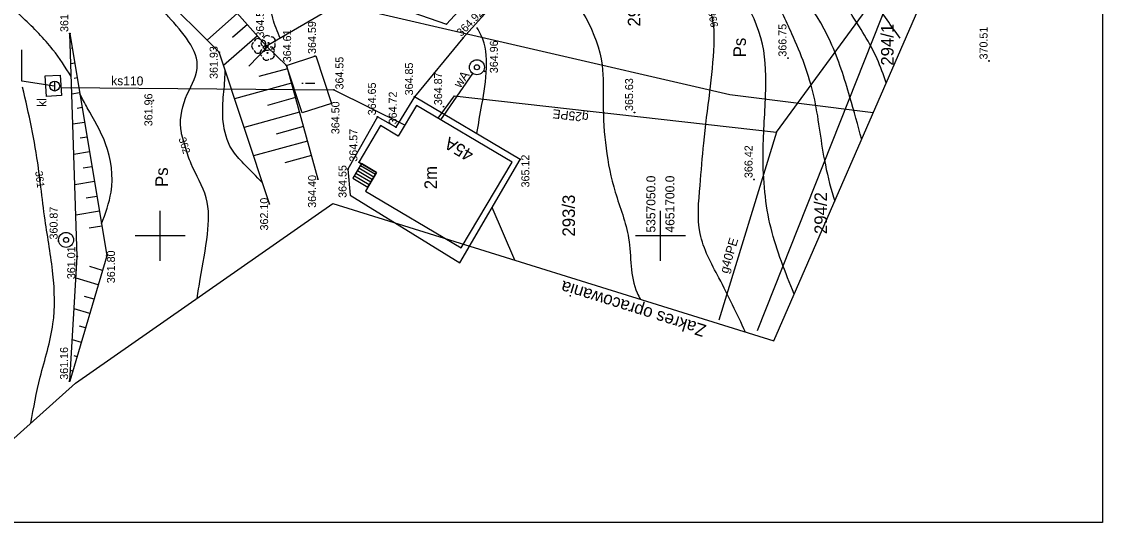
# Model space of a CAD drawing. Extents: x 4635329 to 4651863, y 5356628 to 5367582.
# Drawn here: x 4651223.2 to 4651331.2, y 5356627.7 to 5356677.8 of the extents above; entities that cross this region are included whole.
import ezdxf

# ---------------------------------------------------------------- set-up
doc = ezdxf.new("R2010")
doc.units = 0
for name, color, linetype in [('Level 1', 7, 'Continuous'), ('Level 12', 7, 'Continuous'), ('Level 13', 7, 'Continuous'), ('Level 14', 7, 'Continuous'), ('Level 15', 7, 'Continuous'), ('Level 20', 7, 'Continuous'), ('Level 22', 7, 'Continuous'), ('Level 35', 7, 'Continuous'), ('Level 36', 7, 'Continuous'), ('Level 37', 7, 'Continuous'), ('Level 39', 7, 'Continuous'), ('Level 4', 7, 'Continuous'), ('Level 44', 7, 'Continuous'), ('Level 45', 7, 'Continuous'), ('Level 46', 7, 'Continuous'), ('Level 47', 7, 'Continuous'), ('Level 48', 7, 'Continuous'), ('Level 5', 7, 'Continuous'), ('Level 54', 7, 'Continuous'), ('Level 55', 7, 'Continuous'), ('Level 58', 7, 'Continuous'), ('Level 6', 7, 'Continuous'), ('Level 60', 7, 'Continuous')]:
    doc.layers.add(name, color=color, linetype=linetype)

msp = doc.modelspace()

# ---------------------------------------------------------------- linework, layer by layer
at = {"layer": 'Level 1'}
for p, q in [((4651298.354, 5356645.8610000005), (4651316.177, 5356686.717)), ((4651228.549, 5356641.621), (4651254.266, 5356659.569)), ((4651254.266, 5356659.569), (4651298.354, 5356645.8610000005)), ((4651216.704, 5356631.078), (4651228.549, 5356641.621))]:
    msp.add_line(p, q, dxfattribs=at)
at = {"layer": 'Level 13'}
for points in [[(4651092.18, 5356627.729), (4651092.18, 5356813.355), (4651331.195, 5356813.355), (4651331.195, 5356627.729)], [(4651272.195, 5356663.717), (4651262.635, 5356669.387), (4651260.818, 5356666.323), (4651259.036, 5356667.38), (4651256.87, 5356663.728), (4651258.633, 5356662.682), (4651257.536, 5356660.833000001), (4651267.112, 5356655.151000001)], [(4651272.195, 5356663.717), (4651272.195, 5356663.717)]]:
    msp.add_lwpolyline(points, close=True, dxfattribs=at)
at = {"layer": 'Level 15'}
for p, q in [((4651257.141, 5356663.567), (4651256.273, 5356662.104)), ((4651256.886, 5356663.136), (4651258.3780000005, 5356662.25)), ((4651257.039, 5356663.394), (4651258.531, 5356662.508)), ((4651258.633, 5356662.682), (4651257.141, 5356663.567)), ((4651256.273, 5356662.104), (4651257.765, 5356661.218)), ((4651256.426, 5356662.362), (4651257.9180000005, 5356661.476)), ((4651256.579, 5356662.62), (4651258.071, 5356661.734)), ((4651256.733, 5356662.8780000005), (4651258.225000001, 5356661.992000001)), ((4651257.765, 5356661.218), (4651258.633, 5356662.682))]:
    msp.add_line(p, q, dxfattribs=at)
for points in [[(4651249.6450000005, 5356673.377), (4651252.5770000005, 5356674.333000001), (4651254.125, 5356669.587), (4651251.193, 5356668.631)], [(4651225.6450000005, 5356670.2870000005), (4651225.531, 5356672.323), (4651227.025, 5356672.407), (4651227.139, 5356670.371)]]:
    msp.add_lwpolyline(points, close=True, dxfattribs=at)
at = {"layer": 'Level 20'}
for points in [[(4651283.015, 5356700.977), (4651282.555, 5356699.227), (4651281.905, 5356696.897), (4651273.365, 5356685.887), (4651265.6450000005, 5356677.517)], [(4651267.255, 5356676.097), (4651275.075, 5356684.757), (4651285.735, 5356696.707), (4651287.285, 5356699.227)], [(4651256.195, 5356680.807), (4651265.6450000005, 5356677.517)], [(4651253.4350000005, 5356678.667), (4651247.655, 5356675.297)], [(4651267.255, 5356676.097), (4651262.4350000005, 5356670.237)]]:
    msp.add_lwpolyline(points, dxfattribs=at)
at = {"layer": 'Level 22'}
msp.add_lwpolyline([(4651273.005, 5356663.997), (4651262.4350000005, 5356670.237), (4651260.585, 5356667.207), (4651258.725000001, 5356668.247), (4651255.775, 5356663.017), (4651256.008, 5356660.426), (4651266.98, 5356653.641), (4651273.005, 5356663.997)], dxfattribs=at)
at = {"layer": 'Level 35'}
msp.add_lwpolyline([(4651265.066, 5356667.945), (4651268.25, 5356672.579)], dxfattribs=at)
at = {"layer": 'Level 36'}
msp.add_line((4651226.467, 5356670.82), (4651226.467, 5356671.82), dxfattribs=at)
msp.add_lwpolyline([(4651226.437, 5356671.29), (4651223.181, 5356671.8040000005), (4651223.181, 5356674.936)], dxfattribs=at)
msp.add_circle((4651226.466676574, 5356671.320149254), 0.5, dxfattribs=at)
at = {"layer": 'Level 37'}
msp.add_lwpolyline([(4651227.0940000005, 5356671.175), (4651254.375, 5356670.947), (4651261.4350000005, 5356667.457)], dxfattribs=at)
at = {"layer": 'Level 39'}
for points in [[(4651298.615, 5356666.727), (4651310.795, 5356683.3270000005)], [(4651266.3950000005, 5356670.357), (4651264.783, 5356668.113)], [(4651266.3950000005, 5356670.357), (4651298.615, 5356666.727), (4651292.866, 5356647.9180000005)]]:
    msp.add_lwpolyline(points, dxfattribs=at)
at = {"layer": 'Level 4'}
for p, q in [((4651296.735, 5356646.885), (4651312.251, 5356686.105)), ((4651293.945, 5356670.447), (4651252.965, 5356679.897)), ((4651308.288, 5356668.633), (4651293.945, 5356670.447))]:
    msp.add_line(p, q, dxfattribs=at)
at = {"layer": 'Level 44'}
for centre in [(4651265.6450000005, 5356677.517), (4651227.975000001, 5356676.567), (4651267.255, 5356676.097), (4651247.655, 5356675.297), (4651242.915, 5356674.697), (4651252.465, 5356674.297), (4651299.765, 5356674.107), (4651319.865, 5356673.8270000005), (4651319.865, 5356673.8270000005), (4651249.6450000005, 5356673.377), (4651269.447972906, 5356672.787698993), (4651254.375, 5356670.947), (4651236.325, 5356669.877), (4651254.125, 5356669.587), (4651262.4350000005, 5356670.237), (4651265.345, 5356669.257), (4651284.4350000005, 5356668.677), (4651258.725000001, 5356668.247), (4651260.585, 5356667.207), (4651273.005, 5356663.997), (4651255.775, 5356663.017), (4651256.905, 5356663.707), (4651252.775, 5356662.007), (4651296.375, 5356661.977), (4651247.925, 5356659.557), (4651226.833, 5356655.840658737), (4651228.725000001, 5356654.2870000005), (4651231.675, 5356654.347), (4651227.955, 5356641.8270000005)]:
    msp.add_circle(centre, 0.04, dxfattribs=at)
at = {"layer": 'Level 46'}
for p, q in [((4651292.399, 5356676.979), (4651292.041, 5356679.073)), ((4651239.818, 5356664.316000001), (4651239.172, 5356666.442)), ((4651225.09, 5356661.222), (4651224.855, 5356663.04)), ((4651272.465, 5356653.911), (4651270.197, 5356659.171))]:
    msp.add_line(p, q, dxfattribs=at)
for points in [[(4651300.394, 5356650.538), (4651298.071, 5356657.119), (4651297.283, 5356664.3950000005), (4651297.525, 5356670.398), (4651297.222, 5356675.491), (4651291.339, 5356684.404), (4651287.093, 5356687.193), (4651283.575, 5356689.133), (4651281.998, 5356690.892), (4651281.523, 5356691.985)], [(4651307.135, 5356665.99), (4651305.956, 5356670.216), (4651304.015, 5356675.733), (4651297.646, 5356685.192), (4651295.888, 5356687.799), (4651295.484, 5356688.617000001)], [(4651228.12, 5356672.269), (4651226.297, 5356674.945), (4651223.325, 5356678.098), (4651221.142, 5356680.341), (4651219.686, 5356682.766), (4651219.019, 5356684.282), (4651218.821, 5356685.129)], [(4651310.99, 5356676.097), (4651308.382, 5356679.796), (4651304.957, 5356685.363)], [(4651249.021, 5356676.093), (4651248.274, 5356678.101), (4651248.214, 5356681.739), (4651248.335, 5356683.6790000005), (4651248.335, 5356684.088)], [(4651274.444, 5356684.058), (4651276.507, 5356682.152), (4651281.177, 5356673.421), (4651281.298, 5356669.601), (4651282.502, 5356660.721), (4651283.836, 5356656.113), (4651284.6850000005, 5356650.656), (4651285.015, 5356650.008)], [(4651239.172, 5356666.442), (4651239.132, 5356666.654), (4651239.557, 5356670.11), (4651240.709, 5356673.081), (4651237.858, 5356678.235), (4651236.949, 5356679.265)], [(4651309.598, 5356671.636), (4651308.68, 5356674.0430000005), (4651306.011, 5356678.651000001), (4651305.441, 5356679.573)], [(4651299.187, 5356678.601), (4651300.134000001, 5356676.573), (4651302.317, 5356670.328), (4651303.409, 5356663.901000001), (4651304.313, 5356660.2190000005), (4651304.436, 5356659.8040000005)], [(4651268.653, 5356666.566000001), (4651269.171, 5356669.459), (4651269.626, 5356673.127), (4651269.1110000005, 5356676.371), (4651268.671, 5356677.176)], [(4651295.526000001, 5356646.74), (4651292.863, 5356652.156), (4651290.982, 5356656.583000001), (4651290.982, 5356661.373), (4651291.346, 5356665.617000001), (4651291.953, 5356670.71), (4651292.377, 5356675.44), (4651292.399, 5356676.979)], [(4651247.229, 5356661.659), (4651245.379, 5356663.562), (4651244.166, 5356665.017), (4651243.317, 5356667.745), (4651243.317, 5356670.171), (4651243.499, 5356672.475000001), (4651243.499, 5356672.932)], [(4651224.855, 5356663.04), (4651224.841, 5356663.146), (4651223.266, 5356671.212)], [(4651231.144, 5356657.5370000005), (4651232.097, 5356660.712), (4651231.551, 5356665.562), (4651229.731, 5356669.14), (4651228.979, 5356670.54)], [(4651240.707, 5356650.106), (4651241.012, 5356652.041), (4651241.74, 5356656.528), (4651241.619, 5356660.166), (4651240.103, 5356663.562), (4651239.818, 5356664.316000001)], [(4651224.079, 5356637.643), (4651225.023, 5356642.228), (4651226.297, 5356647.563), (4651226.297, 5356652.535), (4651225.508, 5356657.932), (4651225.09, 5356661.222)]]:
    msp.add_spline(points, degree=3, dxfattribs=at)
at = {"layer": 'Level 48'}
for p, q in [((4651244.742000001, 5356678.5940000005), (4651241.703, 5356675.909)), ((4651245.735, 5356677.47), (4651244.251, 5356676.158)), ((4651246.728, 5356676.346), (4651243.356, 5356673.365)), ((4651228.221, 5356675.087), (4651228.124, 5356675.071)), ((4651247.727, 5356675.227), (4651245.87, 5356673.302)), ((4651228.468, 5356673.608), (4651228.0770000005, 5356673.5430000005)), ((4651249.734, 5356673.0540000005), (4651246.858, 5356672.262)), ((4651228.714, 5356672.1280000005), (4651228.421, 5356672.079)), ((4651250.132, 5356671.607), (4651244.455, 5356670.044)), ((4651228.961, 5356670.648), (4651228.1790000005, 5356670.518)), ((4651250.53, 5356670.161), (4651247.728, 5356669.39)), ((4651229.207, 5356669.169), (4651228.718, 5356669.087)), ((4651250.928, 5356668.715), (4651245.398, 5356667.193)), ((4651229.453, 5356667.689), (4651228.28, 5356667.494)), ((4651251.3270000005, 5356667.269), (4651248.598, 5356666.518)), ((4651229.7, 5356666.21), (4651229.016, 5356666.096)), ((4651251.725000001, 5356665.823), (4651246.342, 5356664.341)), ((4651229.946, 5356664.73), (4651228.382, 5356664.47)), ((4651252.123, 5356664.376), (4651249.468, 5356663.646)), ((4651230.192, 5356663.25), (4651229.313, 5356663.104)), ((4651230.439, 5356661.771), (4651228.484, 5356661.445)), ((4651230.6850000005, 5356660.291), (4651229.61, 5356660.112)), ((4651230.932, 5356658.811), (4651228.586, 5356658.421)), ((4651231.178, 5356657.332), (4651229.907, 5356657.12)), ((4651231.675, 5356654.347), (4651227.995, 5356641.8270000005)), ((4651227.995, 5356641.8270000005), (4651228.725000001, 5356654.247)), ((4651231.252, 5356652.908), (4651229.971, 5356653.284)), ((4651230.829, 5356651.4690000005), (4651228.600000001, 5356652.124)), ((4651230.406, 5356650.03), (4651229.458, 5356650.308)), ((4651229.983, 5356648.591), (4651228.42, 5356649.05)), ((4651229.5600000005, 5356647.151000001), (4651228.945, 5356647.332)), ((4651229.137, 5356645.712), (4651228.239, 5356645.976)), ((4651228.714, 5356644.273), (4651228.431, 5356644.356)), ((4651228.291, 5356642.834), (4651228.058, 5356642.903))]:
    msp.add_line(p, q, dxfattribs=at)
for points in [[(4651247.925, 5356659.557), (4651242.915, 5356674.697), (4651236.735, 5356680.877), (4651232.205, 5356686.657)], [(4651232.205, 5356686.657), (4651243.325, 5356680.197), (4651247.655, 5356675.297), (4651249.6450000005, 5356673.377), (4651252.775, 5356662.007)], [(4651228.725000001, 5356654.2870000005), (4651227.975000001, 5356676.567)], [(4651227.975000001, 5356676.567), (4651231.675, 5356654.347)]]:
    msp.add_lwpolyline(points, dxfattribs=at)
at = {"layer": 'Level 54'}
for centre, radius in [((4651268.675, 5356673.197), 0.7499999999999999), ((4651268.675, 5356673.197), 0.25000000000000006), ((4651227.605, 5356655.947), 0.7500000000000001), ((4651227.605, 5356655.947), 0.25)]:
    msp.add_circle(centre, radius, dxfattribs=at)
at = {"layer": 'Level 55'}
for centre in [(4651246.89837069, 5356675.322033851), (4651247.838258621, 5356675.6251262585), (4651247.747301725, 5356674.624921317)]:
    msp.add_circle(centre, 0.045, dxfattribs=at)
for centre, start, end in [((4651246.782370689, 5356675.678533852), 48.19845000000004, 167.84984166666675), ((4651247.463258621, 5356675.6251262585), 120.14713055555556, 239.85286944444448), ((4651247.201870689, 5356675.542533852), 336.10841111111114, 95.89019166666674), ((4651247.722258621, 5356675.981626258), 48.19845000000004, 167.84984166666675), ((4651248.141758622, 5356675.845626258), 336.10841111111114, 95.89019166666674), ((4651246.52337069, 5356675.322033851), 120.14713055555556, 239.85286944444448), ((4651246.782370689, 5356674.965533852), 192.15015833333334, 311.80155), ((4651247.372301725, 5356674.624921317), 120.14713055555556, 239.85286944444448), ((4651247.201870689, 5356675.101533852), 264.1076444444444, 23.89158888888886), ((4651247.631301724, 5356674.981421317), 48.19845000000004, 167.84984166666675), ((4651247.722258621, 5356675.268626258), 192.15015833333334, 311.80155), ((4651248.050801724, 5356674.845421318), 336.10841111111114, 95.89019166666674), ((4651248.141758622, 5356675.404626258), 264.1076444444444, 23.89158888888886), ((4651247.631301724, 5356674.268421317), 192.15015833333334, 311.80155), ((4651248.050801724, 5356674.404421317), 264.1076444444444, 23.89158888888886)]:
    msp.add_arc(centre, 0.375, start, end, dxfattribs=at)
at = {"layer": 'Level 60'}
for p, q in [((4651237.015, 5356653.847), (4651237.015, 5356658.847)), ((4651287.015, 5356653.847), (4651287.015, 5356658.847)), ((4651239.515, 5356656.347), (4651234.515, 5356656.347)), ((4651289.515, 5356656.347), (4651284.515, 5356656.347))]:
    msp.add_line(p, q, dxfattribs=at)

# ---------------------------------------------------------------- texts
at = {"layer": 'Level 12'}
for p in [(4651295.5600000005, 5356674.194), (4651237.791, 5356661.238)]:
    msp.add_text('Ps', height=1.2499980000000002, rotation=90, dxfattribs=at).set_placement(p)
at = {"layer": 'Level 14'}
for s, p in [('i', (4651252.483, 5356671.409)), ('2m', (4651264.671, 5356661.006))]:
    msp.add_text(s, height=1.2499980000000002, rotation=90, dxfattribs=at).set_placement(p)
at = {"layer": 'Level 35'}
msp.add_text('wA', height=0.9, rotation=55.507222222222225, dxfattribs=at).set_placement((4651267.025, 5356671.0540000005))
at = {"layer": 'Level 37'}
for s, height, rotation, p in [('ks110', 0.8999880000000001, 359.5211638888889, (4651232.115, 5356671.402)), ('kl', 0.9, 90, (4651225.62, 5356669.246))]:
    msp.add_text(s, height=height, rotation=rotation, dxfattribs=at).set_placement(p)
at = {"layer": 'Level 39'}
for s, rotation, p in [('g25PE', 173.57199444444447, (4651279.875, 5356668.600000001)), ('g40PE', 73.00414722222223, (4651293.754, 5356652.533))]:
    msp.add_text(s, height=0.8999880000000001, rotation=rotation, dxfattribs=at).set_placement(p)
at = {"layer": 'Level 45'}
for s, rotation, p in [('361.77', 90, (4651227.825, 5356676.717)), ('364.56', 90, (4651247.399, 5356676.159)), ('364.92', 45.84554722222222, (4651267.116, 5356676.214)), ('364.59', 90, (4651252.587, 5356674.522)), ('366.75', 90, (4651299.615, 5356674.257)), ('370.51', 90, (4651319.715, 5356673.977)), ('370.51', 90, (4651319.715, 5356673.977)), ('364.61', 90, (4651250.101, 5356673.694)), ('361.93', 90, (4651242.765, 5356672.032)), ('364.96', 90, (4651270.769, 5356672.604)), ('364.55', 90, (4651255.331, 5356670.976)), ('364.85', 90, (4651262.285, 5356670.387)), ('364.87', 90, (4651265.195, 5356669.407)), ('364.65', 90, (4651258.575, 5356668.397)), ('365.63', 90, (4651284.285, 5356668.8270000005)), ('361.96', 90, (4651236.2360000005, 5356667.302)), ('364.72', 90, (4651260.6620000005, 5356667.494)), ('364.50', 90, (4651254.9290000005, 5356666.511)), ('364.57', 90, (4651256.725000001, 5356663.766)), ('366.42', 90, (4651296.225000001, 5356662.127)), ('365.12', 90, (4651273.916, 5356661.191000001)), ('364.55', 90, (4651255.64, 5356660.151000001)), ('364.40', 90, (4651252.595, 5356659.159)), ('362.10', 90, (4651247.805, 5356656.892)), ('360.87', 90, (4651226.759000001, 5356655.991)), ('361.01', 90, (4651228.521, 5356652.028)), ('361.80', 90, (4651232.494, 5356651.621)), ('361.16', 90, (4651227.805, 5356641.977))]:
    msp.add_text(s, height=0.7999980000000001, rotation=rotation, dxfattribs=at).set_placement(p)
at = {"layer": 'Level 47'}
for s, height, rotation, p in [('366', 0.7499880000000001, 279.39488888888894, (4651291.785, 5356678.783)), ('362', 0.75, 287.4253555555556, (4651238.84, 5356666.069)), ('361', 0.75, 277.33576111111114, (4651224.513, 5356662.783))]:
    msp.add_text(s, height=height, rotation=rotation, dxfattribs=at).set_placement(p)
at = {"layer": 'Level 5'}
for s, p in [('293/1', (4651285.008, 5356677.266)), ('294/1', (4651310.32, 5356673.356)), ('293/3', (4651278.475000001, 5356656.283)), ('294/2', (4651303.664, 5356656.536))]:
    msp.add_text(s, height=1.2499980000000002, rotation=90, dxfattribs=at).set_placement(p)
at = {"layer": 'Level 58'}
for s, p in [(' 5357050.0 ', (4651286.515, 5356656.347)), (' 4651700.0 ', (4651288.415, 5356656.347))]:
    msp.add_text(s, height=0.9, rotation=90, dxfattribs=at).set_placement(p)
at = {"layer": 'Level 6'}
for s, rotation, p in [('45A', 149.32798055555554, (4651268.465, 5356664.767)), ('Zakres opracowania', 162.72829722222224, (4651291.674, 5356647.414))]:
    msp.add_text(s, height=1.2499980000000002, rotation=rotation, dxfattribs=at).set_placement(p)

doc.saveas('drawing.dxf')
